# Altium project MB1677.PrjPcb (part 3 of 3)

## Sheet STM32_microcontroller_IOs.SchDoc: STM32 microcontroller IOs
size A3; Date: Not used; ApprovedBy: Not used; CheckedBy: Not used; Author: Not used; CompanyName: STMicroelectronics; DrawnBy: Not used; Engineer: Not used; Organization: Not used; Address1: Not used; Address2: Not used; Address3: Not used; Address4: Not used; DocumentNumber: 3; Revision: Not used; SheetNumber: 3; SheetTotal: 15
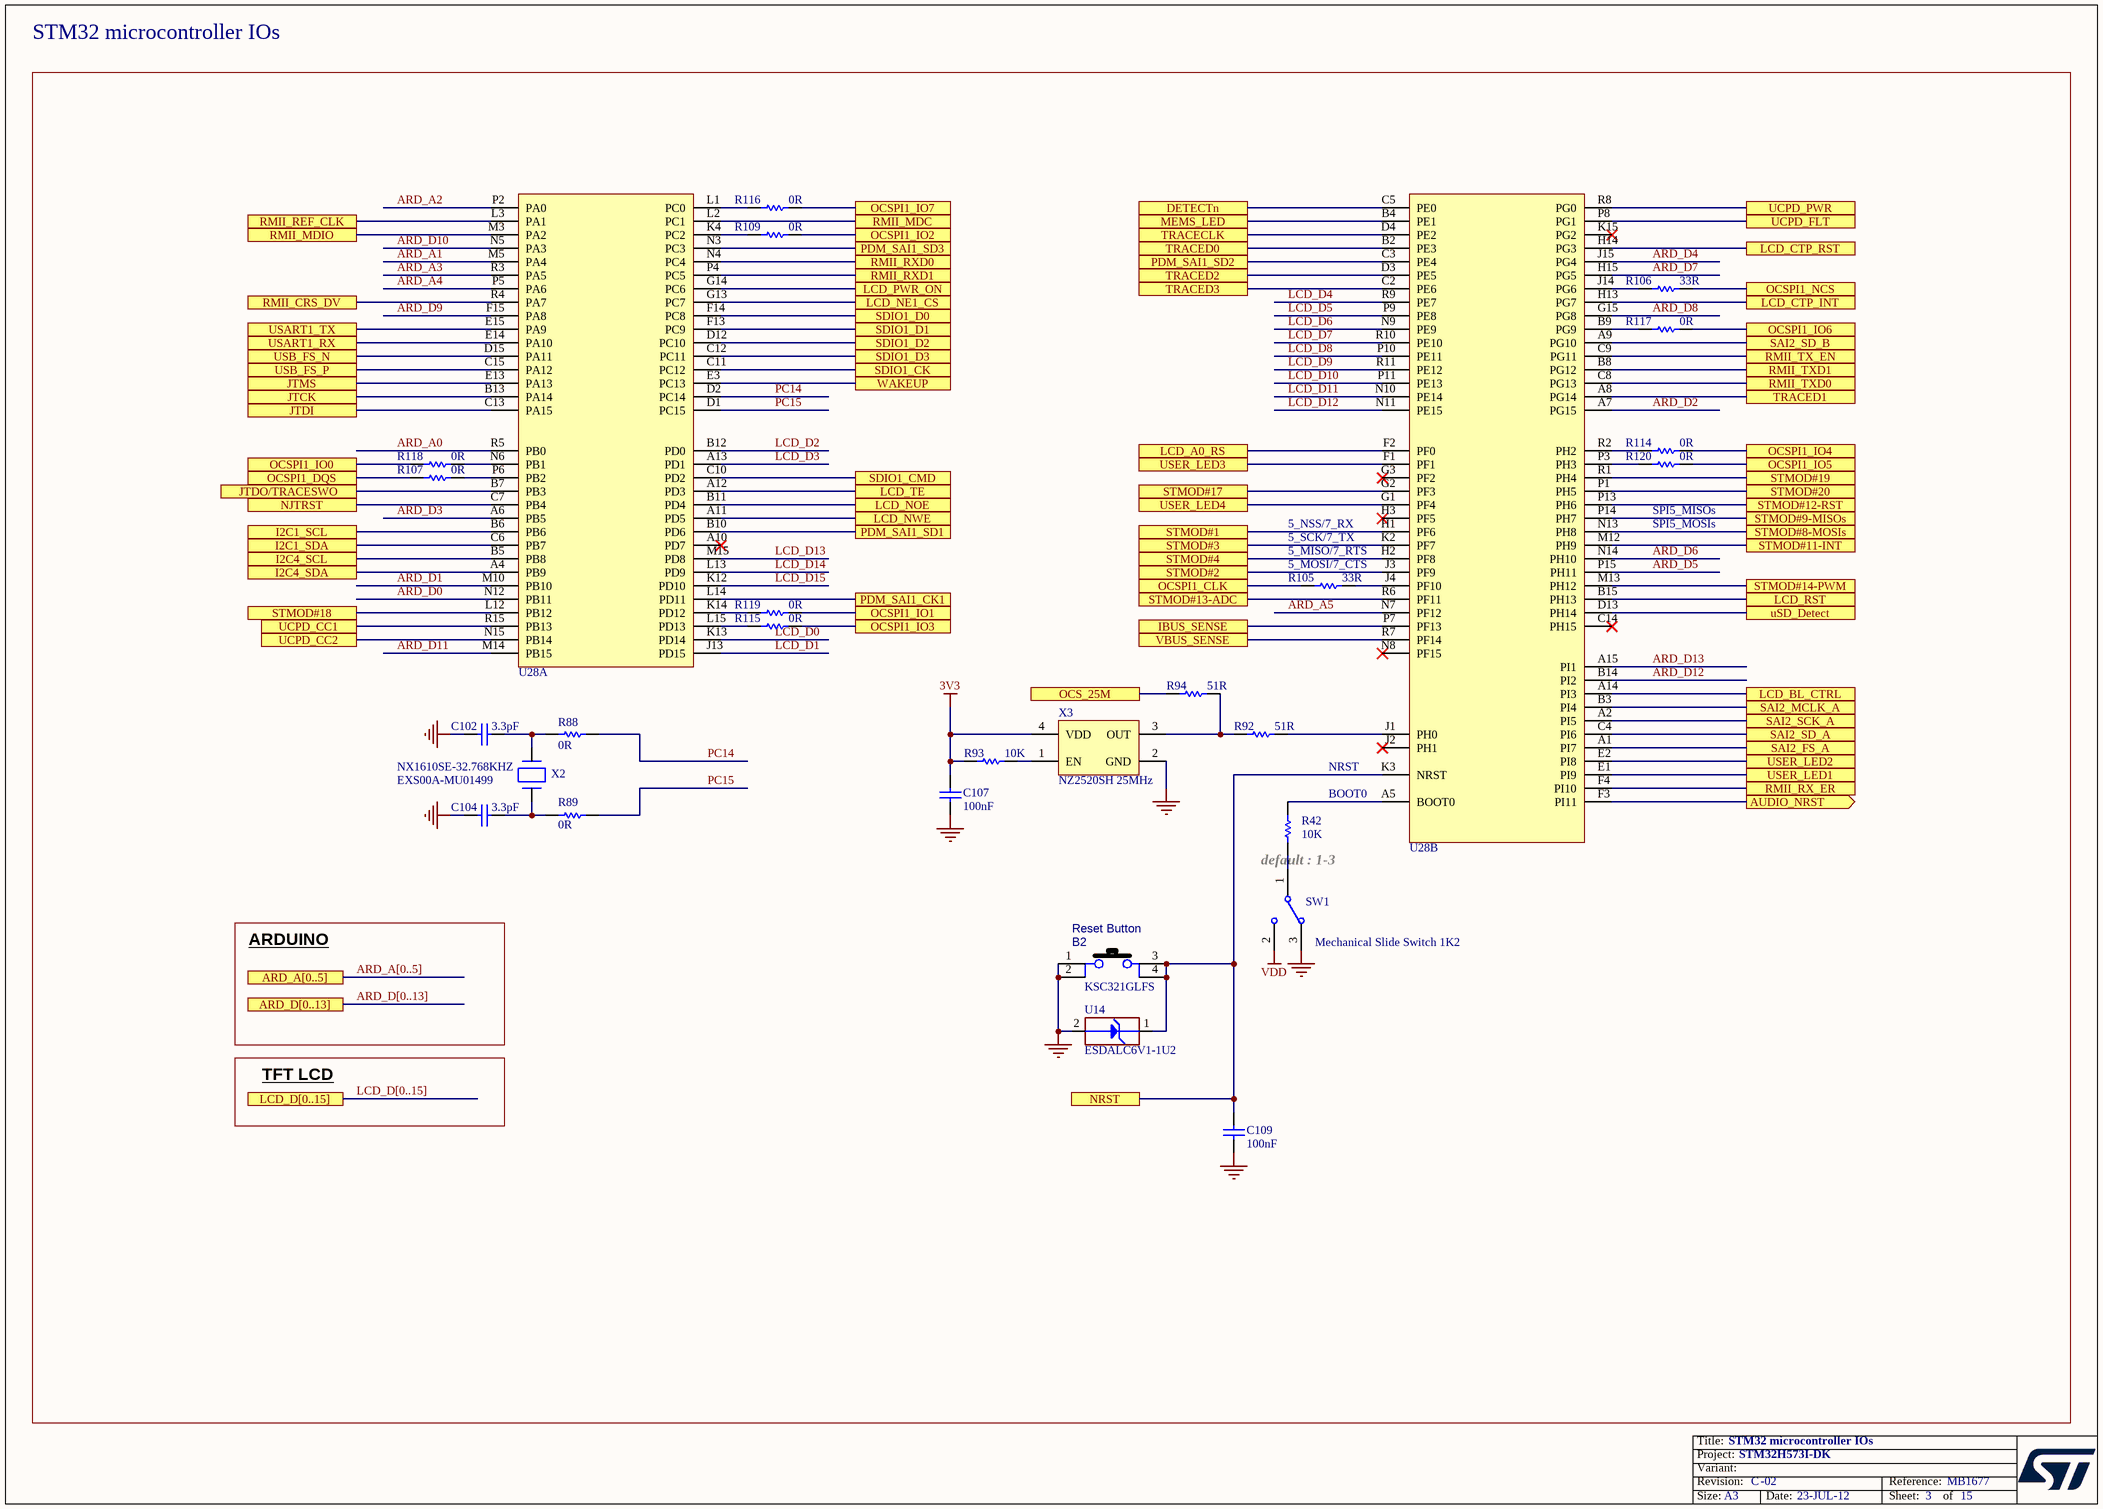
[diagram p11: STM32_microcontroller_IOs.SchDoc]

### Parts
B2  value KSC321GLFS  [SWI_C&K_KSC321GLFS_BLACK]  (hidden comment: SW_BLACK_KSC321GLFS)
C102  value 3.3pF  [C0402]  (hidden comment: Capacitor)
C104  value 3.3pF  [C0402]  (hidden comment: Capacitor)
C107  value 100nF  [C0402]  (hidden comment: Capacitor)
C109  value 100nF  [C0402]  (hidden comment: Capacitor)
R42  value 10K  [R0402]  (hidden comment: Resistor)
R88  value 0R  [R0402]  (hidden comment: Resistor)
R89  value 0R  [R0402]  (hidden comment: Resistor)
R92  value 51R  [R0402]  (hidden comment: Resistor)
R93  value 10K  [R0402]  (hidden comment: Resistor)
R94  value 51R  [R0402]  (hidden comment: Resistor)
R105  value 33R  [R0402]  (hidden comment: Resistor)
R106  value 33R  [R0402]  (hidden comment: Resistor)
R107  value 0R  [R0402]  (hidden comment: Resistor)
R109  value 0R  [R0402]  (hidden comment: Resistor)
R114  value 0R  [R0402]  (hidden comment: Resistor)
R115  value 0R  [R0402]  (hidden comment: Resistor)
R116  value 0R  [R0402]  (hidden comment: Resistor)
R117  value 0R  [R0402]  (hidden comment: Resistor)
R118  value 0R  [R0402]  (hidden comment: Resistor)
R119  value 0R  [R0402]  (hidden comment: Resistor)
R120  value 0R  [R0402]  (hidden comment: Resistor)
SW1  value Mechanical Slide Switch 1K2  [SWI_EAO_09-03290-01_EXTENDED_STRAIGHT_BLACK]  (hidden comment: SW_MECA_1K2)
U14  value ESDALC6V1-1U2  [ESD_ST0201]  (hidden comment: ESD-TRANSIL)
U28  STM32H573IIK3Q  [ICC_UFBGA201_176+25_10X10_P065]  (value not drawn)  (parts A,B of 3)
X2  XTAL_2_PINS  [CRY_NX1610SE_2P]  (value not drawn)
X3  value NZ2520SH 25MHz  [OSC_NDK_NZ2520SB_4P]  (hidden comment: OSCILLATOR_4_PINS)

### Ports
ARD_A[0..5], ARD_D[0..13], AUDIO_NRST (out), DETECTn, I2C1_SCL, I2C1_SDA, I2C4_SCL, I2C4_SDA, IBUS_SENSE, JTCK, JTDI, JTDO/TRACESWO, JTMS, LCD_A0_RS, LCD_BL_CTRL, LCD_CTP_INT, LCD_CTP_RST, LCD_D[0..15], LCD_NE1_CS, LCD_NOE, LCD_NWE, LCD_PWR_ON, LCD_RST, LCD_TE, MEMS_LED, NJTRST, NRST, OCS_25M, OCSPI1_CLK, OCSPI1_DQS, OCSPI1_IO0, OCSPI1_IO1, OCSPI1_IO2, OCSPI1_IO3, OCSPI1_IO4, OCSPI1_IO5, OCSPI1_IO6, OCSPI1_IO7, OCSPI1_NCS, PDM_SAI1_CK1, PDM_SAI1_SD1, PDM_SAI1_SD2, PDM_SAI1_SD3, RMII_CRS_DV, RMII_MDC, RMII_MDIO, RMII_REF_CLK, RMII_RX_ER, RMII_RXD0, RMII_RXD1, RMII_TX_EN, RMII_TXD0, RMII_TXD1, SAI2_FS_A, SAI2_MCLK_A, SAI2_SCK_A, SAI2_SD_A, SAI2_SD_B, SDIO1_CK, SDIO1_CMD, SDIO1_D0, SDIO1_D1, SDIO1_D2, SDIO1_D3, STMOD#1, STMOD#2, STMOD#3, STMOD#4, STMOD#8-MOSIs, STMOD#9-MISOs, STMOD#11-INT, STMOD#12-RST, STMOD#13-ADC, STMOD#14-PWM, STMOD#17, STMOD#18, STMOD#19, STMOD#20, TRACECLK, TRACED0, TRACED1, TRACED2, TRACED3, UCPD_CC1, UCPD_CC2, UCPD_FLT, UCPD_PWR, USART1_RX, USART1_TX, USB_FS_N, USB_FS_P, uSD_Detect, USER_LED1, USER_LED2, USER_LED3, USER_LED4, VBUS_SENSE, WAKEUP

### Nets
3V3: C107.2 R93.1 X3.4(VDD)
GND: B2.1 B2.2 C102.1 C104.1 C107.1 C109.1 SW1.3 U14.2(GND) X3.2(GND)
VDD: SW1.2
ARD_A0: U28.R5(PB0)
ARD_A1: U28.M5(PA4)
ARD_A2: U28.P2(PA0)
ARD_A3: U28.R3(PA5)
ARD_A4: U28.P5(PA6)
ARD_A5: U28.N7(PF12)
ARD_D0: U28.N12(PB11)
ARD_D1: U28.M10(PB10)
ARD_D2: U28.A7(PG15)
ARD_D3: U28.A6(PB5)
ARD_D4: U28.J15(PG4)
ARD_D5: U28.P15(PH11)
ARD_D6: U28.N14(PH10)
ARD_D7: U28.H15(PG5)
ARD_D8: U28.G15(PG8)
ARD_D9: U28.F15(PA8)
ARD_D10: U28.N5(PA3)
ARD_D11: U28.M14(PB15)
ARD_D12: U28.B14(PI2)
ARD_D13: U28.A15(PI1)
AUDIO_NRST: U28.F3(PI11) ; port AUDIO_NRST
DETECTn: U28.C5(PE0) ; port DETECTn
I2C1_SCL: U28.B6(PB6) ; port I2C1_SCL
I2C1_SDA: U28.C6(PB7) ; port I2C1_SDA
I2C4_SCL: U28.B5(PB8) ; port I2C4_SCL
I2C4_SDA: U28.A4(PB9) ; port I2C4_SDA
IBUS_SENSE: U28.P7(PF13) ; port IBUS_SENSE
JTCK: U28.B13(PA14) ; port JTCK
JTDI: U28.C13(PA15) ; port JTDI
JTDO: U28.B7(PB3) ; port JTDO/TRACESWO
JTMS: U28.E13(PA13) ; port JTMS
LCD_A0_RS: U28.F2(PF0) ; port LCD_A0_RS
LCD_BL_CTRL: U28.A14(PI3) ; port LCD_BL_CTRL
LCD_CTP_INT: U28.H13(PG7) ; port LCD_CTP_INT
LCD_CTP_RST: U28.H14(PG3) ; port LCD_CTP_RST
LCD_D0: U28.K13(PD14)
LCD_D1: U28.J13(PD15)
LCD_D2: U28.B12(PD0)
LCD_D3: U28.A13(PD1)
LCD_D4: U28.R9(PE7)
LCD_D5: U28.P9(PE8)
LCD_D6: U28.N9(PE9)
LCD_D7: U28.R10(PE10)
LCD_D8: U28.P10(PE11)
LCD_D9: U28.R11(PE12)
LCD_D10: U28.P11(PE13)
LCD_D11: U28.N10(PE14)
LCD_D12: U28.N11(PE15)
LCD_D13: U28.M15(PD8)
LCD_D14: U28.L13(PD9)
LCD_D15: U28.K12(PD10)
LCD_NE1_CS: U28.G13(PC7) ; port LCD_NE1_CS
LCD_NOE: U28.B11(PD4) ; port LCD_NOE
LCD_NWE: U28.A11(PD5) ; port LCD_NWE
LCD_PWR_ON: U28.G14(PC6) ; port LCD_PWR_ON
LCD_RST: U28.B15(PH13) ; port LCD_RST
LCD_TE: U28.A12(PD3) ; port LCD_TE
MEMS_LED: U28.B4(PE1) ; port MEMS_LED
NJTRST: U28.C7(PB4) ; port NJTRST
NRST: B2.3 B2.4 C109.2 U14.1(IO1) U28.K3(NRST) ; port NRST
OCS_25M: R94.1 ; port OCS_25M
OCSPI1_CLK: R105.1 ; port OCSPI1_CLK
OCSPI1_DQS: R107.1 ; port OCSPI1_DQS
OCSPI1_IO0: R118.1 ; port OCSPI1_IO0
OCSPI1_IO1: R119.2 ; port OCSPI1_IO1
OCSPI1_IO2: R109.2 ; port OCSPI1_IO2
OCSPI1_IO3: R115.2 ; port OCSPI1_IO3
OCSPI1_IO4: R114.2 ; port OCSPI1_IO4
OCSPI1_IO5: R120.2 ; port OCSPI1_IO5
OCSPI1_IO6: R117.2 ; port OCSPI1_IO6
OCSPI1_IO7: R116.2 ; port OCSPI1_IO7
OCSPI1_NCS: R106.2 ; port OCSPI1_NCS
PC14: R88.2 U28.D2(PC14)
PC15: R89.2 U28.D1(PC15)
PDM_SAI1_CK1: U28.L14(PD11) ; port PDM_SAI1_CK1
PDM_SAI1_SD1: U28.B10(PD6) ; port PDM_SAI1_SD1
PDM_SAI1_SD2: U28.C3(PE4) ; port PDM_SAI1_SD2
PDM_SAI1_SD3: U28.N3(PC3) ; port PDM_SAI1_SD3
PMOD11: U28.M12(PH9) ; port STMOD#11-INT
PMOD12: U28.P13(PH6) ; port STMOD#12-RST
RMII_CRS_DV: U28.R4(PA7) ; port RMII_CRS_DV
RMII_MDC: U28.L2(PC1) ; port RMII_MDC
RMII_MDIO: U28.M3(PA2) ; port RMII_MDIO
RMII_REF_CLK: U28.L3(PA1) ; port RMII_REF_CLK
RMII_RX_ER: U28.F4(PI10) ; port RMII_RX_ER
RMII_RXD0: U28.N4(PC4) ; port RMII_RXD0
RMII_RXD1: U28.P4(PC5) ; port RMII_RXD1
RMII_TX_EN: U28.C9(PG11) ; port RMII_TX_EN
RMII_TXD0: U28.C8(PG13) ; port RMII_TXD0
RMII_TXD1: U28.B8(PG12) ; port RMII_TXD1
SAI2_FS_A: U28.A1(PI7) ; port SAI2_FS_A
SAI2_MCLK_A: U28.B3(PI4) ; port SAI2_MCLK_A
SAI2_SCK_A: U28.A2(PI5) ; port SAI2_SCK_A
SAI2_SD_A: U28.C4(PI6) ; port SAI2_SD_A
SAI2_SD_B: U28.A9(PG10) ; port SAI2_SD_B
SDIO1_CK: U28.C11(PC12) ; port SDIO1_CK
SDIO1_CMD: U28.C10(PD2) ; port SDIO1_CMD
SDIO1_D0: U28.F14(PC8) ; port SDIO1_D0
SDIO1_D1: U28.F13(PC9) ; port SDIO1_D1
SDIO1_D2: U28.D12(PC10) ; port SDIO1_D2
SDIO1_D3: U28.C12(PC11) ; port SDIO1_D3
STMOD#1: U28.H1(PF6) ; port STMOD#1
STMOD#2: U28.J3(PF9) ; port STMOD#2
STMOD#3: U28.K2(PF7) ; port STMOD#3
STMOD#4: U28.H2(PF8) ; port STMOD#4
STMOD#8-MOSIs: U28.N13(PH8) ; port STMOD#8-MOSIs
STMOD#9-MISOs: U28.P14(PH7) ; port STMOD#9-MISOs
STMOD#13-ADC: U28.R6(PF11) ; port STMOD#13-ADC
STMOD#14-PWM: U28.M13(PH12) ; port STMOD#14-PWM
STMOD#17: U28.G2(PF3) ; port STMOD#17
STMOD#18: U28.L12(PB12) ; port STMOD#18
STMOD#19: U28.R1(PH4) ; port STMOD#19
STMOD#20: U28.P1(PH5) ; port STMOD#20
TRACECLK: U28.D4(PE2) ; port TRACECLK
TRACED0: U28.B2(PE3) ; port TRACED0
TRACED1: U28.A8(PG14) ; port TRACED1
TRACED2: U28.D3(PE5) ; port TRACED2
TRACED3: U28.C2(PE6) ; port TRACED3
UCPD_CC1: U28.R15(PB13) ; port UCPD_CC1
UCPD_CC2: U28.N15(PB14) ; port UCPD_CC2
UCPD_FLT: U28.P8(PG1) ; port UCPD_FLT
UCPD_PWR: U28.R8(PG0) ; port UCPD_PWR
USART1_RX: U28.E14(PA10) ; port USART1_RX
USART1_TX: U28.E15(PA9) ; port USART1_TX
USB_FS_N: U28.D15(PA11) ; port USB_FS_N
USB_FS_P: U28.C15(PA12) ; port USB_FS_P
uSD_Detect: U28.D13(PH14) ; port uSD_Detect
USER_LED1: U28.E1(PI9) ; port USER_LED1
USER_LED2: U28.E2(PI8) ; port USER_LED2
USER_LED3: U28.F1(PF1) ; port USER_LED3
USER_LED4: U28.G1(PF4) ; port USER_LED4
VBUS_SENSE: U28.R7(PF14) ; port VBUS_SENSE
WAKEUP: U28.E3(PC13) ; port WAKEUP
NetC102_2: C102.2 R88.1 X2.2(X2)
NetC104_2: C104.2 R89.1 X2.1(X1)
NetR42_1: R42.1 U28.A5(BOOT0)
NetR42_2: R42.2 SW1.1
NetR92_1: R92.1 R94.2 X3.3(OUT)
NetR92_2: R92.2 U28.J1(PH0)
NetR93_2: R93.2 X3.1(EN)
NetR105_2: R105.2 U28.J4(PF10)
NetR106_1: R106.1 U28.J14(PG6)
NetR107_2: R107.2 U28.P6(PB2)
NetR109_1: R109.1 U28.K4(PC2)
NetR114_1: R114.1 U28.R2(PH2)
NetR115_1: R115.1 U28.L15(PD13)
NetR116_1: R116.1 U28.L1(PC0)
NetR117_1: R117.1 U28.B9(PG9)
NetR118_2: R118.2 U28.N6(PB1)
NetR119_1: R119.1 U28.K14(PD12)
NetR120_1: R120.1 U28.P3(PH3)

Not connected (* = marked no-connect by the designer): U28 A10(PD7)* C14(PH15)* G3(PF2)* H3(PF5)* J2(PH1)* K15(PG2)* N8(PF15)*

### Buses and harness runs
bus ARD_A[0..5] = port ARD_A[0..5]
bus ARD_D[0..13] = port ARD_D[0..13]
bus LCD_D[0..15] = port LCD_D[0..15]

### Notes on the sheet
- STM32 microcontroller IOs
- SPI5_MISOs
- 5_NSS/7_RX
- 5_SCK/7_TX
- (near R105) 5_MISO/7_RTS
- (near R105) 5_MOSI/7_CTS
- SPI5_MOSIs
- EXS00A-MU01499
- NX1610SE-32.768KHZ
- NRST
- BOOT0
- (near R42) default : 1-3
- ARDUINO
- (near B2) Reset Button
- TFT LCD

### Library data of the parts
B2 = MCD-00175: Switch HW BLACK High3.5mm 2Newtons; Part_Type: Misc; Part_Preference: Recommended; Manufacturer: C&K; Component_Country_Of_Origin: France; ShowFields: YES; ID: 2692
C102 C104 = MCD-01775: Capacitor, MLCC, 3.3pF, 50V, NPO, +/-0.1pF, 0402, T=0.5mm; Part_Preference: Recommended; Manufacturer: YAGEO; Manufacturer_Part_Number: CC0402BRNPO9BN3R3; Component_Country_Of_Origin: China; ShowFields: YES; ID: 3875
C107 = MCD-00102: Capacitor, MLCC, 100nF, 16V, X7R, 10%, 0402, T=0,5mm; Manufacturer_Part_Number: CC0402KRX7R7BB104; Manufacturer: YAGEO; Alternate_Manufacturer_Part_Number: GCM155R71C104KA55D; Alternate_Manufacturer: MURATA; ECCN_US: EAR99; ECCN_EU: NEC; Provided_By: SUBCO
C109 = MCD-00006: Capacitor, MLCC, 100nF, 16V, X7R, 10%, 0402, T=0.5mm; Manufacturer_Part_Number: CC0402KRX7R7BB104; Manufacturer: YAGEO; Alternate_Manufacturer_Part_Number: GCM155R71C104KA55D; Alternate_Manufacturer: MURATA; Provided_By: SUBCO
R42 = MCD-00053: Resistor,10K,0402,1%,1/16W; Manufacturer_Part_Number: RC0402FR-0710KL; Manufacturer: YAGEO; Provided_By: SUBCO
R88 R89 R107 R109 R114-R120 = MCD-00052: Resistor,0R,0402,5%,1/16W; Manufacturer_Part_Number: RC0402JR-070RL; Manufacturer: YAGEO; Provided_By: SUBCO
R92 R94 = MCD-00485: Resistor,51R,0402,1%,1/16W; Manufacturer_Part_Number: RC0402FR-0751RL; Manufacturer: YAGEO; ECCN_US: EAR99; ECCN_EU: NEC; Provided_By: SUBCO
R93 = MCD-00053: Resistor,10K,0402,1%,1/16W; Manufacturer_Part_Number: RC0402FR-0710KL; Manufacturer: YAGEO; BMS_Part_Number: 9131590; ECCN_US: EAR99; ECCN_EU: NEC; Provided_By: SUBCO
R105 R106 = MCD-00455: Resistor,33R,0402,1%,1/16W; Manufacturer_Part_Number: RC0402FR-0733RL; Manufacturer: YAGEO; Provided_By: SUBCO; ECCN_US: EAR99; ECCN_EU: NEC
SW1 = MCD-00566: Mechanical Slide Switches 1K2 BLK ACT GOLD STRT MNT; Part_Type: Misc; Manufacturer_Part_Number: 09.03290.01; Manufacturer: EAO; Provided_By: SUBCO
U14 = MCD-00170: ESD protection 6V1; Part_Type: Diode; Manufacturer: STMICROELECTRONICS; BMS_Part_Number: 9151132; Provided_By: SUBCO with ST control
U28 = MCD-02379: MCU, Arm Cortex-M33, 250MHz, 32-bit MCU, 2MB Flash, 640KB SRAM, Crypto; Part_Type: IC; Manufacturer: STMICROELECTRONICS; Part_Preference: Recommended
X2 = MCD-02291: Crystal, 32.768kHz, 9pF, +/-20ppm, 70KR, 1.6x1mm; Part_Type: Crystal_Osc; Part_Preference: Recommended; Manufacturer: NDK; Manufacturer_Part_Number: NX1610SE-32.768KHZ-EXS00A-MU01499; Component_Country_Of_Origin: Unknown; ShowFields: YES; ID: 4391
X3 = MCD-00597: Oscillator 25Mhz, +-50ppm, Vcc:3.3V typ, square wave: [0.1Vcc;0.9Vcc], Enable pin, SMD; Part_Type: Crystal_Osc; Manufacturer_Part_Number: NZ2520SH 25MHz END4869C; Manufacturer: NDK; Alternate_Manufacturer_Part_Number: NZ2520SB 25MHz END4869B; BMS_Part_Number: 9157050; ECCN_US: EAR99; ECCN_EU: NEC; Provided_By: SUBCO

## Sheet USB-PD.SchDoc: USB-PD
size A3; Date: Not used; ApprovedBy: Not used; CheckedBy: Not used; Author: Not used; CompanyName: STMicroelectronics; DrawnBy: Not used; Engineer: Not used; Organization: Not used; Address1: Not used; Address2: Not used; Address3: Not used; Address4: Not used; DocumentNumber: 13; Revision: Not used; SheetNumber: 13; SheetTotal: 15
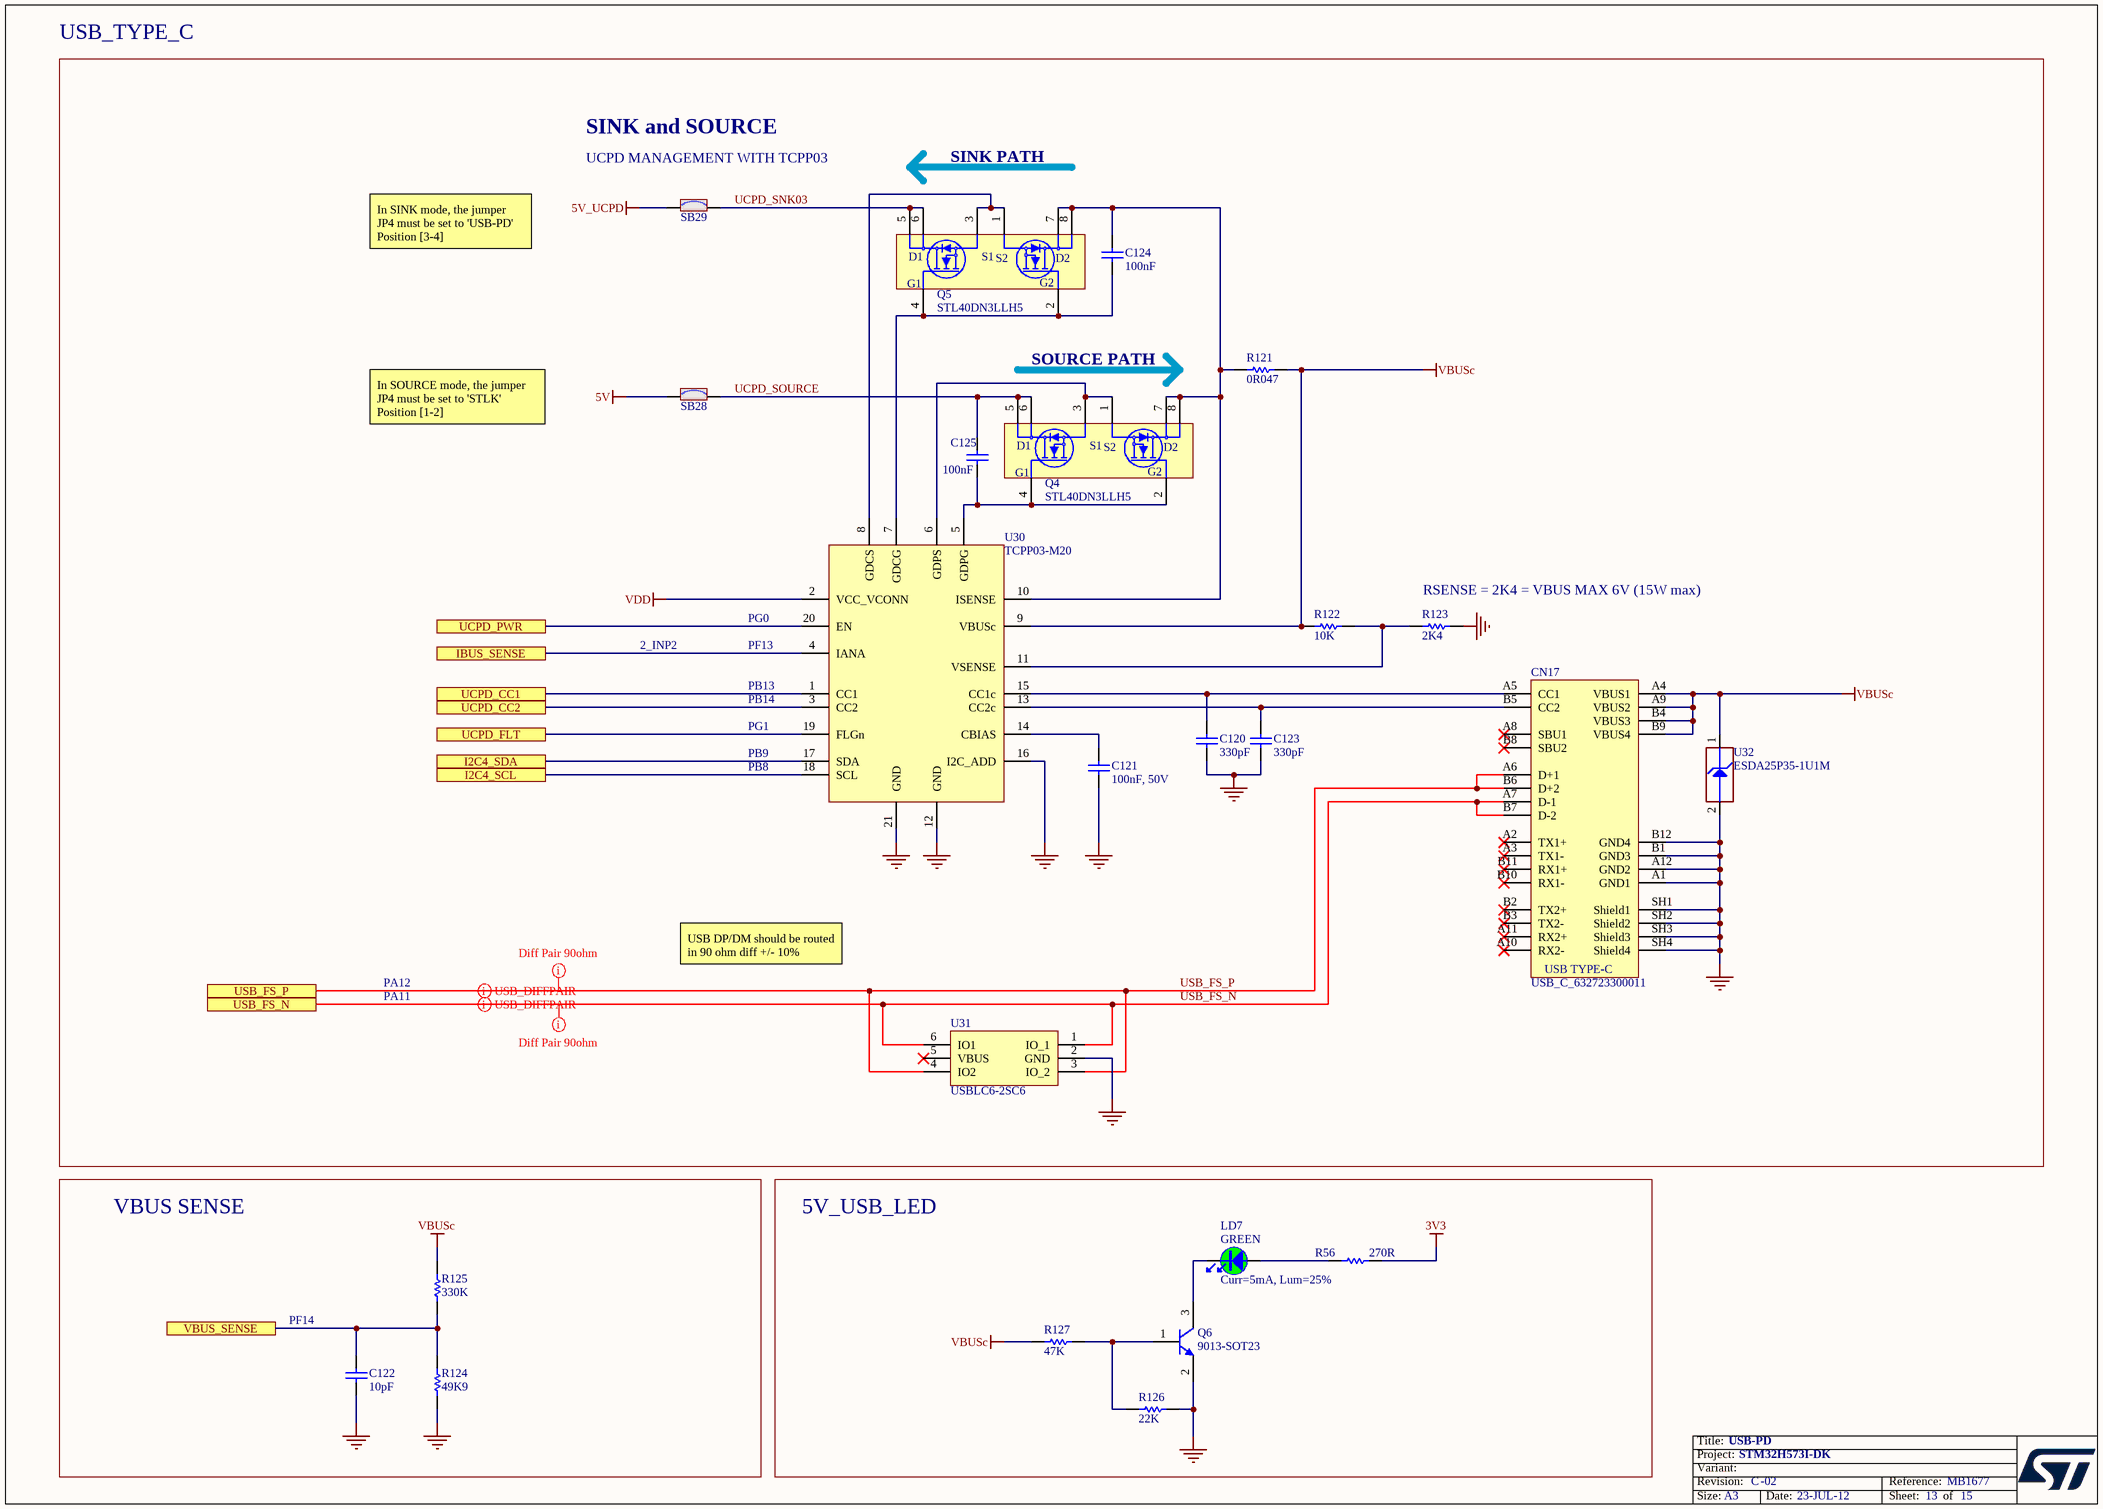
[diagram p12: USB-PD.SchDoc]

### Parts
C120  value 330pF  [C0402]  (hidden comment: Capacitor)
C121  value 100nF, 50V  [C0603]
C122  value 10pF  [C0402]
C123  value 330pF  [C0402]  (hidden comment: Capacitor)
C124  value 100nF  [C0603]
C125  value 100nF  [C0603]
CN17  value USB_C_632723300011  [CON_USB-TYPEC_WE_632723300011]  (hidden comment: USB_TYPE_C_Receptacle)
LD7  value GREEN  [LED_0603_OSRAM_LG-Q396-PS-35_GREEN_1A2K_H0P4]
Q4  STL40DN3LLH5  [PowerFLAT_5x6]
Q5  STL40DN3LLH5  [PowerFLAT_5x6]
Q6  value 9013-SOT23  [NPN_SOT23]
R56  value 270R  [R0603]
R121  value 0R047  [R0805_H0P5]  (hidden comment: Resistor)
R122  value 10K  [R0402]  (hidden comment: Resistor)
R123  value 2K4  [R0402]  (hidden comment: Resistor)
R124  value 49K9  [R0603]
R125  value 330K  [R0603]
R126  value 22K  [R0603]
R127  value 47K  [R0603]
SB28  SB_ON  [SOLDER-BRIDGE_R0603-0R]  (value not drawn)
SB29  SB_ON  [SOLDER-BRIDGE_R0603-0R]  (value not drawn)
U30  TCPP03-M20  [ICC_QFN20-EPAD_4X4_P050]
U31  USBLC6-2SC6  [ESD_SOT23-6L]
U32  value ESDA25P35-1U1M  [ESD_QFN1610_2N_1K_2A]

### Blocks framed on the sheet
VBUS SENSE: C122 R124 R125
5V_USB_LED: LD7 Q6 R56 R126 R127

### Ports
I2C4_SCL, I2C4_SDA, IBUS_SENSE, UCPD_CC1, UCPD_CC2, UCPD_FLT, UCPD_PWR, USB_FS_N, USB_FS_P, VBUS_SENSE

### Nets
3V3: R56.2
5V: SB28.1
5V_UCPD: SB29.1
GND: C120.1 C121.2 C122.1 C123.1 CN17.A1(GND1) CN17.A12(GND2) CN17.B1(GND3) CN17.B12(GND4) CN17.SH1(Shield1) CN17.SH2(Shield2) CN17.SH3(Shield3) CN17.SH4(Shield4) Q6.2(E) R123.2 R124.1 R126.2 U30.12(GND) U30.16(I2C_ADD) U30.21(GND) U31.2(GND) U32.2(GND)
VBUSc: CN17.A4(VBUS1) CN17.A9(VBUS2) CN17.B4(VBUS3) CN17.B9(VBUS4) R121.1 R122.1 R125.2 R127.1 U30.9(VBUSc) U32.1(IO1)
VDD: U30.2(VCC_VCONN)
I2C4_SCL: U30.18(SCL) ; port I2C4_SCL
I2C4_SDA: U30.17(SDA) ; port I2C4_SDA
IBUS_SENSE: U30.4(IANA) ; port IBUS_SENSE
UCPD_CC1: U30.1(CC1) ; port UCPD_CC1
UCPD_CC2: U30.3(CC2) ; port UCPD_CC2
UCPD_FLT: U30.19(FLGn) ; port UCPD_FLT
UCPD_PWR: U30.20(EN) ; port UCPD_PWR
UCPD_SNK03: Q5.5(D1) Q5.6(D1) SB29.2
UCPD_SOURCE: C125.2 Q4.5(D1) Q4.6(D1) SB28.2
USB_FS_N: CN17.A7(D-1) CN17.B7(D-2) U31.1(IO_1) U31.6(IO1) ; port USB_FS_N
USB_FS_P: CN17.A6(D+1) CN17.B6(D+2) U31.3(IO_2) U31.4(IO2) ; port USB_FS_P
VBUS_SENSE: C122.2 R124.2 R125.1 ; port VBUS_SENSE
NetC120_2: C120.2 CN17.A5(CC1) U30.15(CC1c)
NetC121_1: C121.1 U30.14(CBIAS)
NetC123_2: C123.2 CN17.B5(CC2) U30.13(CC2c)
NetC124_1: C124.1 Q5.2(G2) Q5.4(G1) U30.7(GDCG)
NetC124_2: C124.2 Q4.7(D2) Q4.8(D2) Q5.7(D2) Q5.8(D2) R121.2 U30.10(ISENSE)
NetC125_1: C125.1 Q4.2(G2) Q4.4(G1) U30.5(GDPG)
NetLD7_1: LD7.1 R56.1
NetLD7_2: LD7.2 Q6.3(C)
NetQ4_1: Q4.1(S2) Q4.3(S1) U30.6(GDPS)
NetQ5_1: Q5.1(S2) Q5.3(S1) U30.8(GDCS)
NetQ6_1: Q6.1(B) R126.1 R127.2
NetR122_2: R122.2 R123.1 U30.11(VSENSE)

Not connected (* = marked no-connect by the designer): CN17 A2(TX1+)* A3(TX1-)* A8(SBU1)* A10(RX2-)* A11(RX2+)* B2(TX2+)* B3(TX2-)* B8(SBU2)* B10(RX1-)* B11(RX1+)*; U31 5(VBUS)*

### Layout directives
mark named Diff Pair 90ohm: USB_FS_N, USB_FS_P
differential pair: USB_FS_N, USB_FS_P

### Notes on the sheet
- USB_TYPE_C
- (near SB29) UCPD MANAGEMENT WITH TCPP03
- SINK and SOURCE
- SINK PATH
- In SINK mode, the jumper JP4 must be set to 'USB-PD' Position [3-4]
- SOURCE PATH
- In SOURCE mode, the jumper JP4 must be set to 'STLK' Position [1-2]
- 2_INP2
- PF13
- PG0
- (near R123) RSENSE = 2K4 = VBUS MAX 6V (15W max)
- PB13
- PB14
- PB9
- PB8
- PG1
- PA12
- USB DP/DM should be routed in 90 ohm diff +/- 10%
- PA11
- PF14
- Curr=5mA, Lum=25%

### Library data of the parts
C120 C123 = MCD-01579: Capacitor, MLCC, 330pF, 50V, NPO, +/-5%, 0402, T=0,5mm; Part_Preference: Recommended; Manufacturer: YAGEO; Manufacturer_Part_Number: CC0402JRNPO9BN331
C121 = MCD-01099: Capacitor,100nF,50V,X7R,10%,0603; Manufacturer_Part_Number: CC0603KRX7R9BB104; Manufacturer: YAGEO; BMS_Part_Number: 9142278; Provided_By: SUBCO
C122 = MCD-00015: Capacitor, MLCC, 10pF, 50V, NPO, 5%, 0402, T=0,5mm; Manufacturer_Part_Number: CC0402JRNPO9BN100; Manufacturer: YAGEO; Provided_By: subcon; Initial_Board_Reference: MB1274
C124 C125 = MCD-00211: Capacitor, MLCC, 100nF, 16V, X7R, 10%, 0603, T=0,8mm; Manufacturer_Part_Number: CC0603KRX7R7BB104; Manufacturer: YAGEO; Provided_By: Subcon; Initial_Board_Reference: MB1319
CN17 = MCD-02273: USB_TypeC, 24pins, RA, TH, T=1.9mm (USB certified); Part_Type: Connector; Part_Preference: Recommended; Manufacturer: WURTH ELEKTRONIK; Manufacturer_Part_Number: 632723300011; Component_Country_Of_Origin: China; ShowFields: YES; ID: 4373
LD7 = MCD-00588: LED Green, 0603 SMD, Forward Voltage Typ=2V, Max=2.5V; Part_Type: Display; Manufacturer_Part_Number: LG Q396-PS-35; Manufacturer: OSRAM OPTO SEMICONDUCTORS; Alternate_Manufacturer_Part_Number: VLMTG1300-GS08; Alternate_Manufacturer: VISHAY SEMICONDUCTOR OPTO DIVISION; Provided_By: Subcon; Initial_Board_Reference: MB1331
Q4 Q5 = MCD-02152: Dual N-channel 30 V, 0.016 Ω typ., 40 A, STripFET™ H5 Power MOSFET; Part_Type: Transistor; Manufacturer: STMICROELECTRONICS; ECCN_US: EAR99; ECCN_EU: NEC; Provided_By: SUBCO
Q6 = MCD-00073: NPN Bipolar Transistor; Part_Type: IC; Manufacturer_Part_Number: BSR14; Manufacturer: NXP; ECCN_US: EAR99; ECCN_EU: NEC; Provided_By: Subcon; Initial_Board_Reference: MB1274
R56 = MCD-00442: Resistor,270R,0603,1%,1/10W; Manufacturer_Part_Number: RC0603FR-07270RL; Manufacturer: YAGEO; Provided_By: Subcon
R121 = MCD-02151: Current Detection Resistor, 0R047, 0805, 1%, 1/4W; Manufacturer_Part_Number: RL0805FR-7W0R047L; Manufacturer: YAGEO; ECCN_US: NEC; ECCN_EU: EAR99; Provided_By: SUBCO
R122 = MCD-00053: Resistor,10K,0402,1%,1/16W; BMS_Part_Number: 9131590; Part_Preference: Recommended; Manufacturer: YAGEO; Manufacturer_Part_Number: RC0402FR-0710KL
R123 = MCD-00433: Resistor,2K4,0402,1%,1/16W; Part_Preference: Recommended; Manufacturer: YAGEO; Manufacturer_Part_Number: RC0402FR-072K4L
R124 = MCD-01171: Resistor,49K9,0603,1%; Manufacturer_Part_Number: RC0603FR-0749K9L; Manufacturer: YAGEO; Provided_By: Subcon; Initial_Board_Reference: MB1397
R125 = MCD-00458: Resistor,330K,0603,1%,1/10W; Manufacturer_Part_Number: RC0603FR-07330KL; Manufacturer: YAGEO; Provided_By: Subcon
R126 = MCD-00430: Resistor,22K,0603,1%,1/10W; Manufacturer_Part_Number: RC0603FR-0722KL; Manufacturer: YAGEO; Provided_By: Subcon
R127 = MCD-00222: Resistor,47K,0603,1%,1/10W; Manufacturer_Part_Number: RC0603FR-0747KL; Manufacturer: YAGEO; Provided_By: Subcon; Initial_Board_Reference: MB1319
SB28 SB29 = MCD-00071: Solder Bridge ON; Part_Type: Mechanical; Manufacturer_Part_Number: RC0603JR-070RL; Manufacturer: YAGEO; Provided_By: SUBCO
U30 = MCD-02130: USB Type-C Port Protection for USB DRP Power Delivery, PPS compliant; Part_Type: IC; Manufacturer: STMICROELECTRONICS; ECCN_US: EAR99; ECCN_EU: NEC; Provided_By: SUBCO with ST control
U31 = MCD-00163: Very low capacitance ESD protection; Part_Type: IC; Manufacturer: STMICROELECTRONICS; BMS_Part_Number: 9151075; ECCN_US: EAR99; ECCN_EU: NEC; Provided_By: SUBCO with ST control
U32 = MCD-01207: High power Transient voltage suppressor:25V/35A EOS and ESD transients protection.; Part_Type: Diode; Manufacturer: STMICROELECTRONICS; BMS_Part_Number: 9179045; ECCN_US: EAR99; ECCN_EU: NEC; Provided_By: SUBCO with ST control

## Sheet microSDcard.SchDoc: microSD Card
size A4; Date: Not used; ApprovedBy: Not used; CheckedBy: Not used; Author: Not used; CompanyName: STMicroelectronics; DrawnBy: Not used; Engineer: Not used; Organization: Not used; Address1: Not used; Address2: Not used; Address3: Not used; Address4: Not used; DocumentNumber: 7; Revision: Not used; SheetNumber: 7; SheetTotal: 15
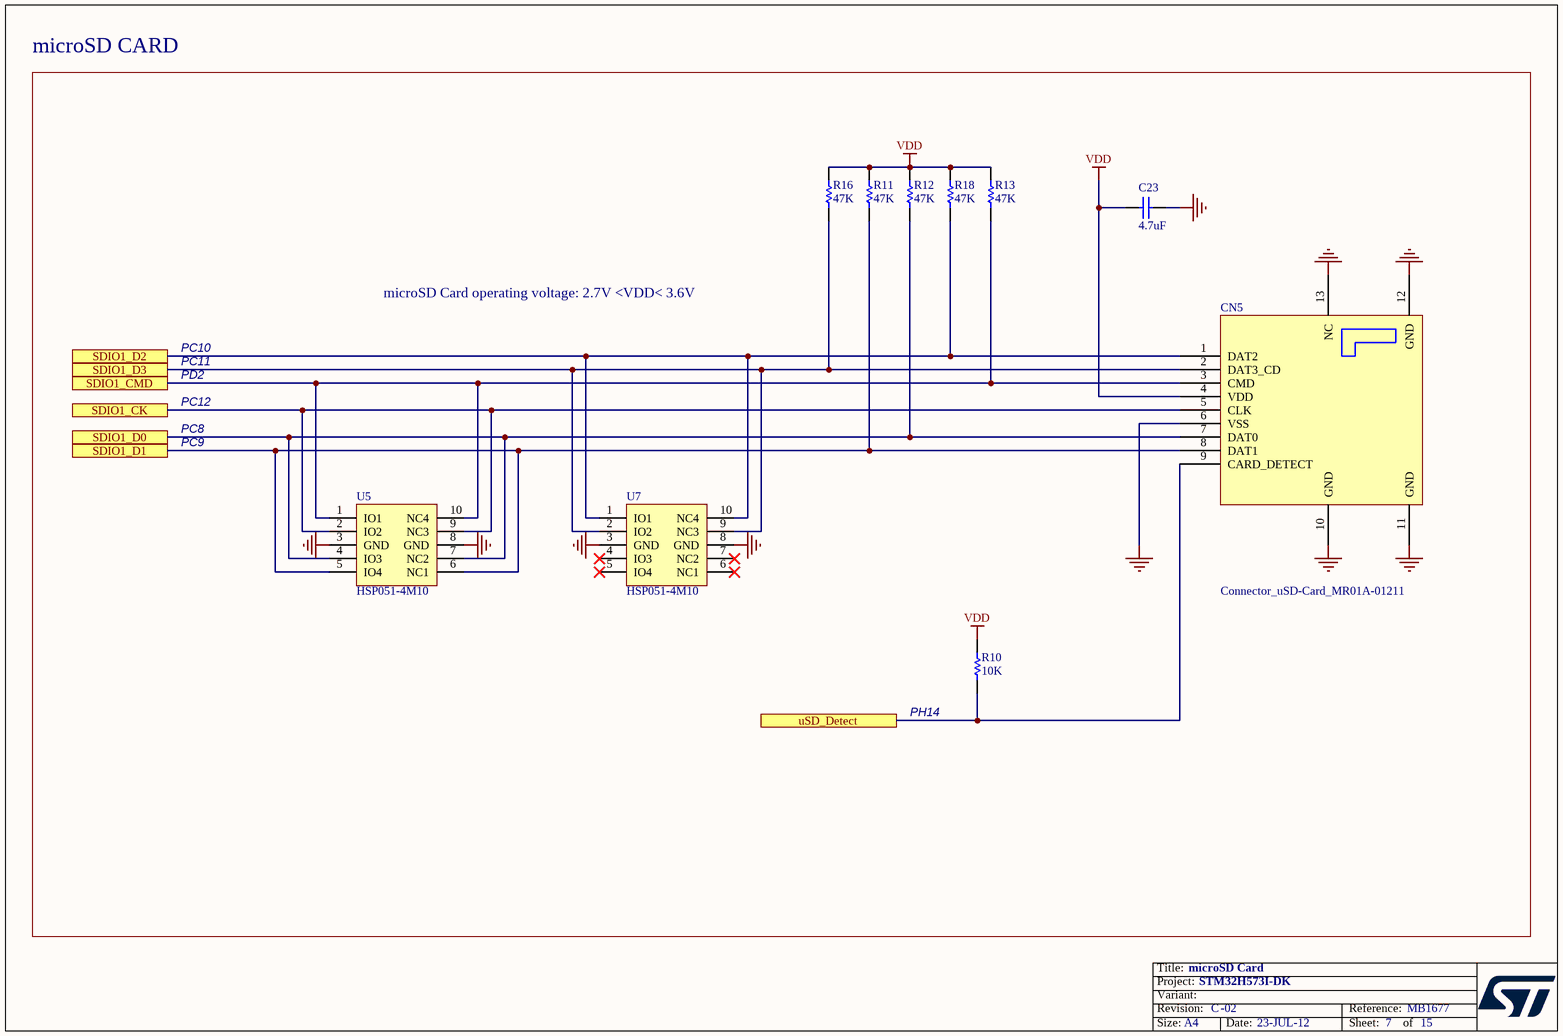
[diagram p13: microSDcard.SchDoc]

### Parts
C23  value 4.7uF  [C0603_H0P8]  (hidden comment: Capacitor)
CN5  value Connector_uSD-Card_MR01A-01211  [CON_MICROSD_ATOM_MR01A-01211]  (hidden comment: MR01A-01211)
R10  value 10K  [R0603]  (hidden comment: Resistor)
R11  value 47K  [R0402]  (hidden comment: Resistor)
R12  value 47K  [R0402]  (hidden comment: Resistor)
R13  value 47K  [R0402]  (hidden comment: Resistor)
R16  value 47K  [R0402]  (hidden comment: Resistor)
R18  value 47K  [R0402]  (hidden comment: Resistor)
U5  HSP051-4M10  [ESD_UQFN-10L_2P5X1_P050]
U7  HSP051-4M10  [ESD_UQFN-10L_2P5X1_P050]

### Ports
SDIO1_CK, SDIO1_CMD, SDIO1_D0, SDIO1_D1, SDIO1_D2, SDIO1_D3, uSD_Detect

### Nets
GND: C23.2 CN5.6(VSS) CN5.10(GND) CN5.11(GND) CN5.12(GND) CN5.13(NC) U5.3(GND) U5.8(GND) U7.3(GND) U7.8(GND)
VDD: C23.1 CN5.4(VDD) R10.2 R11.2 R12.2 R13.2 R16.2 R18.2
SDIO1_CK: CN5.5(CLK) U5.2(IO2) U5.9(NC3) ; port SDIO1_CK
SDIO1_CMD: CN5.3(CMD) R13.1 U5.1(IO1) U5.10(NC4) ; port SDIO1_CMD
SDIO1_D0: CN5.7(DAT0) R12.1 U5.4(IO3) U5.7(NC2) ; port SDIO1_D0
SDIO1_D1: CN5.8(DAT1) R11.1 U5.5(IO4) U5.6(NC1) ; port SDIO1_D1
SDIO1_D2: CN5.1(DAT2) R18.1 U7.1(IO1) U7.10(NC4) ; port SDIO1_D2
SDIO1_D3: CN5.2(DAT3_CD) R16.1 U7.2(IO2) U7.9(NC3) ; port SDIO1_D3
uSD_Detect: CN5.9(CARD_DETECT) R10.1 ; port uSD_Detect

Not connected (* = marked no-connect by the designer): U7 4(IO3)* 5(IO4)* 6(NC1)* 7(NC2)*

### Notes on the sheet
- microSD CARD
- microSD Card operating voltage: 2.7V <VDD< 3.6V
- PC10
- PC11
- PD2
- PC8
- PC9
- PC12
- (near R10) PH14

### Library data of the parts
C23 = MCD-01721: Capacitor, 4.7uF, 10V, X5R, 10%, 0603, T=0.8mm; Manufacturer_Part_Number: CC0603KRX5R6BB475; Manufacturer: YAGEO; Provided_By: SUBCO
CN5 = MCD-00653: Connector_uSD Card, Top Mnt Push-Push; Part_Preference: Recommended; Manufacturer: ATOM; Component_Country_Of_Origin: Unknown; ShowFields: YES; ID: 3087
R10 = MCD-00220: Resistor,10K,0603,1%,1/10W; Manufacturer_Part_Number: RC0603FR-0710KL; Manufacturer: YAGEO; Provided_By: SUBCO
R11-R13 R16 R18 = MCD-00063: Resistor,47K,0402,1%,1/16W; Manufacturer_Part_Number: RC0402FR-0747KL; Manufacturer: YAGEO; Provided_By: SUBCO
U5 U7 = MCD-00667: 4-line ESD protection for high speed lines; Part_Type: Diode; Manufacturer: STMICROELECTRONICS; BMS_Part_Number: 9179041; Provided_By: SUBCO with ST control

## Sheet NOR Flash memory.SchDoc: NOR Flash memory
size A4; Date: Not used; ApprovedBy: Not used; CheckedBy: Not used; Author: Not used; CompanyName: STMicroelectronics; DrawnBy: Not used; Engineer: Not used; Organization: Not used; Address1: Not used; Address2: Not used; Address3: Not used; Address4: Not used; DocumentNumber: 6; Revision: Not used; SheetNumber: 6; SheetTotal: 15
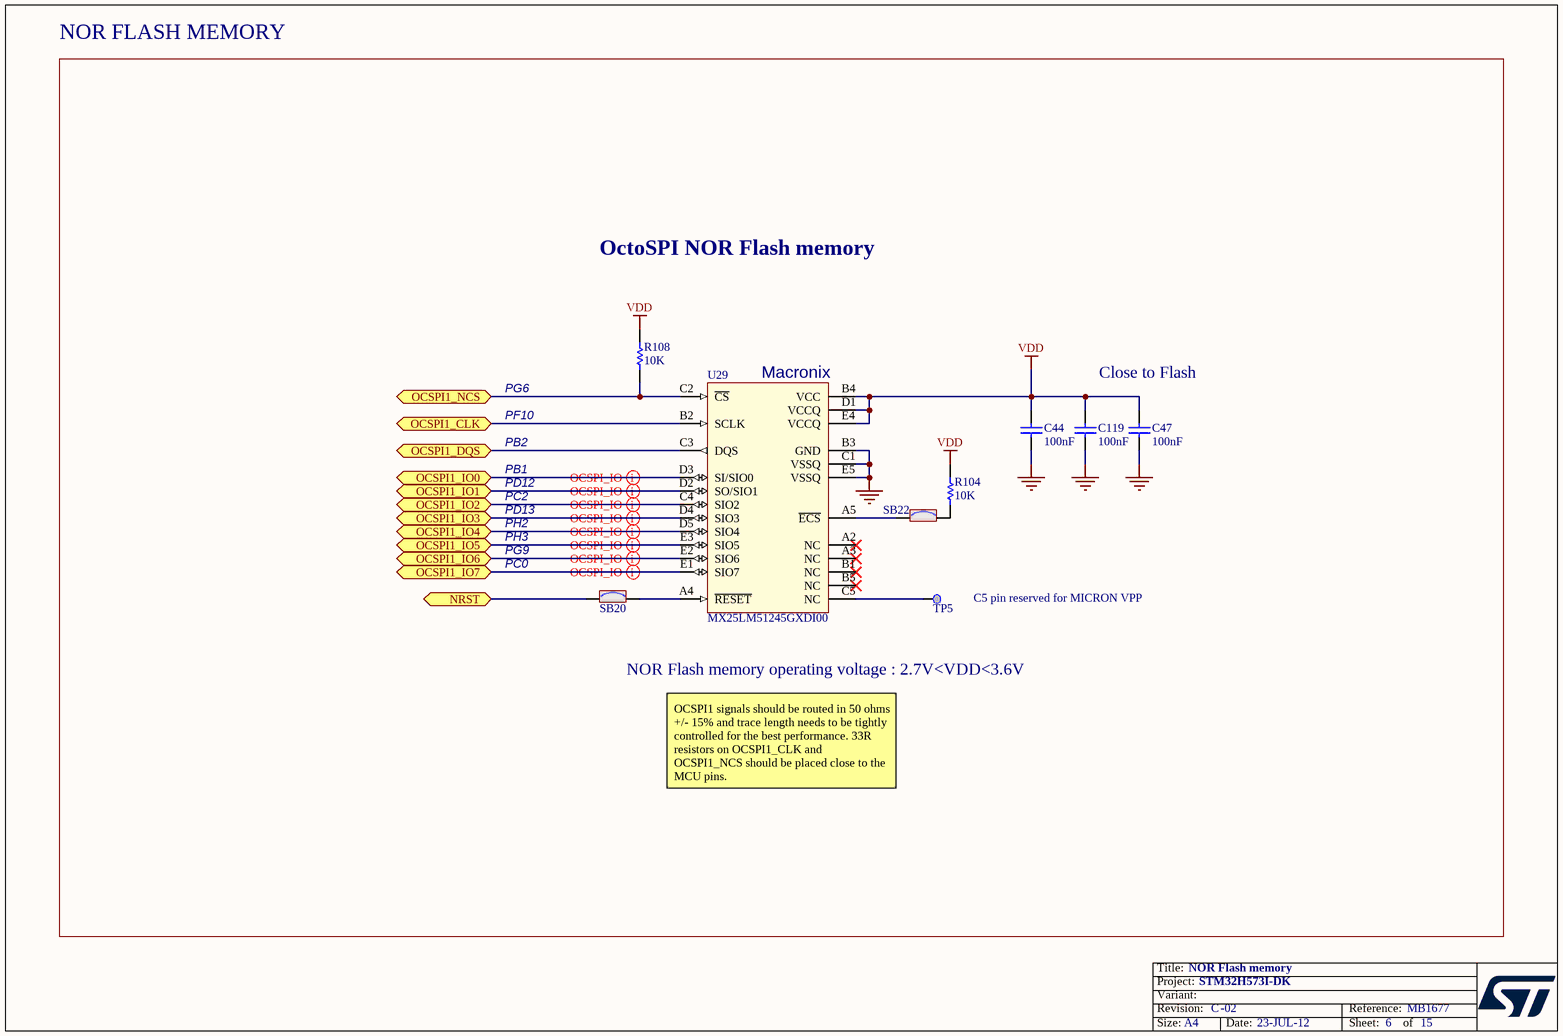
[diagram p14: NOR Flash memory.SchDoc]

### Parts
C44  value 100nF  [C0402]  (hidden comment: Capacitor)
C47  value 100nF  [C0402]  (hidden comment: Capacitor)
C119  value 100nF  [C0402]  (hidden comment: Capacitor)
R104  value 10K  [R0402]  (hidden comment: Resistor)
R108  value 10K  [R0402]  (hidden comment: Resistor)
SB20  SB_ON  [SOLDER-BRIDGE_R0603-0R]  (value not drawn)
SB22  SB_ON  [SOLDER-BRIDGE_R0603-0R]  (value not drawn)
TP5  Test Point  [TP_SMD_1MM]  (value not drawn)  (no BOM)
U29  MX25LM51245GXDI00  [ICC_BGA24_5X5-BALL-ARRAY_6X8_P1]

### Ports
NRST (bidir), OCSPI1_CLK (bidir), OCSPI1_DQS (bidir), OCSPI1_IO0 (bidir), OCSPI1_IO1 (bidir), OCSPI1_IO2 (bidir), OCSPI1_IO3 (bidir), OCSPI1_IO4 (bidir), OCSPI1_IO5 (bidir), OCSPI1_IO6 (bidir), OCSPI1_IO7 (bidir), OCSPI1_NCS (bidir)

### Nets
GND: C44.1 C47.1 C119.1 U29.B3(GND) U29.C1(VSSQ) U29.E5(VSSQ)
VDD: C44.2 C47.2 C119.2 R104.2 R108.1 U29.B4(VCC) U29.D1(VCCQ) U29.E4(VCCQ)
NRST: SB20.1 ; port NRST
OCSPI1_CLK: U29.B2(SCLK) ; port OCSPI1_CLK
OCSPI1_DQS: U29.C3(DQS) ; port OCSPI1_DQS
OCSPI1_IO0: U29.D3(SI/SIO0) ; port OCSPI1_IO0
OCSPI1_IO1: U29.D2(SO/SIO1) ; port OCSPI1_IO1
OCSPI1_IO2: U29.C4(SIO2) ; port OCSPI1_IO2
OCSPI1_IO3: U29.D4(SIO3) ; port OCSPI1_IO3
OCSPI1_IO4: U29.D5(SIO4) ; port OCSPI1_IO4
OCSPI1_IO5: U29.E3(SIO5) ; port OCSPI1_IO5
OCSPI1_IO6: U29.E2(SIO6) ; port OCSPI1_IO6
OCSPI1_IO7: U29.E1(SIO7) ; port OCSPI1_IO7
OCSPI1_NCS: R108.2 U29.C2(~{CS}) ; port OCSPI1_NCS
NetR104_1: R104.1 SB22.2
NetSB20_2: SB20.2 U29.A4(~{RESET})
NetSB22_1: SB22.1 U29.A5(~{ECS})
NetTP5_1: TP5.1 U29.C5(NC)

Not connected (* = marked no-connect by the designer): U29 A2(NC)* A3(NC)* B1(NC)* B5(NC)*

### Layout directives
rule Undefined; rule ? ; rule ? : OCSPI1_IO0, OCSPI1_IO1, OCSPI1_IO2, OCSPI1_IO3, OCSPI1_IO4, OCSPI1_IO5, OCSPI1_IO6, OCSPI1_IO7

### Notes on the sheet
- NOR FLASH MEMORY
- OctoSPI NOR Flash memory
- (near U29) Macronix
- Close to Flash
- PG6
- PF10
- PB2
- PB1
- PD13
- PC2
- PD12
- PH3
- PH2
- PG9
- PC0
- (near TP5) C5 pin reserved for MICRON VPP
- NOR Flash memory operating voltage : 2.7V<VDD<3.6V
- OCSPI1 signals should be routed in 50 ohms +/- 15% and trace length needs to be tightly controlled for the best performance. 33R resistors on OCSPI1_CLK and OCSPI1_NCS should be placed close to the MCU pins.

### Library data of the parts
C44 C47 C119 = MCD-00102: Capacitor, MLCC, 100nF, 16V, X7R, 10%, 0402, T=0,5mm; Manufacturer_Part_Number: CC0402KRX7R7BB104; Manufacturer: YAGEO; Alternate_Manufacturer_Part_Number: GCM155R71C104KA55D; Alternate_Manufacturer: MURATA; Provided_By: SUBCO
R104 R108 = MCD-00053: as R42 on sheet STM32_microcontroller_IOs
SB20 SB22 = MCD-00071: as SB28 on sheet USB-PD
TP5 = MCD-00074: Test Point 1mm; Part_Type: Misc; Part_Preference: Recommended
U29 = MCD-00246: Memory,Octo-SPI-NOR,512Mb,2048x16,133MHz,3V,DTR,BGA24, CMOS MXSMIO; Part_Type: IC; Manufacturer: MACRONIX; ECCN_US: 3A991.b.1.a; Provided_By: SUBCO

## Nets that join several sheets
1V8: Audio_Codec (8 pins), Board_power (JP2.3 SB10.2 TP2.1)
3V3: Audio_Codec (C67.2 CN2.2 CN2.19 U23.2), LCD (Q3.2 R99.1), Peripherals (6 pins), Arduino (CN14.5 R27.2), Ethernet (L1.2), Board_power (6 pins), STM32_microcontroller_power (SB14.1), STM32_microcontroller_IOs (C107.2 R93.1 X3.4), USB-PD (R56.2)
5V: LCD (R49.1 R103.1), Peripherals (CN3.6 CN3.15), Arduino (CN14.4), STLINK_V3EC (R64.2), Board_power (8 pins), USB-PD (SB28.1)
5V_STLK: STLINK_V3EC (6 pins), Board_power (JP4.1)
5V_UCPD: STLINK_V3EC (D4.1), Board_power (JP4.3), USB-PD (SB29.1)
5V_VIN: Arduino (R90.2), STLINK_V3EC (D3.1), Board_power (5 pins)
GND: Audio_Codec (34 pins), LCD (24 pins), Peripherals (7 pins), Arduino (6 pins), JTAG (13 pins), Ethernet (19 pins), STLINK_V3EC (121 pins), Board_power (15 pins), STM32_microcontroller_power (64 pins), STM32_microcontroller_IOs (9 pins), USB-PD (21 pins), microSDcard (10 pins), NOR Flash memory (6 pins)
VBUS_STLK: STLINK_V3EC (12 pins), Board_power (JP4.7)
VDD: Audio_Codec (7 pins), LCD (Q2.2 R100.1), Peripherals (B1.1 B1.2), Arduino (CN14.7), JTAG (CN1.1 CN18.1), Ethernet (7 pins), STLINK_V3EC (9 pins), Board_power (JP2.2), STM32_microcontroller_power (JP6.1), STM32_microcontroller_IOs (SW1.2), USB-PD (U30.2), microSDcard (8 pins), NOR Flash memory (8 pins)
VIN: Arduino (CN14.1), Board_power (C32.2 JP3.1 U8.3)
VREFP: Arduino (C110.1 R95.2), STM32_microcontroller_power (C35.2 C36.2 R21.2 U28.N1)
ARD_A0: Arduino (CN16.6), STM32_microcontroller_IOs (U28.R5)
ARD_A1: Arduino (CN16.5), STM32_microcontroller_IOs (U28.M5)
ARD_A2: Arduino (CN16.4), STM32_microcontroller_IOs (U28.P2)
ARD_A3: Arduino (CN16.3), STM32_microcontroller_IOs (U28.R3)
ARD_A4: Arduino (SB24.1), STM32_microcontroller_IOs (U28.P5)
ARD_A5: Arduino (SB23.1), STM32_microcontroller_IOs (U28.N7)
ARD_D0: Arduino (CN15.1), STM32_microcontroller_IOs (U28.N12)
ARD_D1: Arduino (CN15.2), STM32_microcontroller_IOs (U28.M10)
ARD_D2: Arduino (CN15.3), STM32_microcontroller_IOs (U28.A7)
ARD_D3: Arduino (CN15.4), STM32_microcontroller_IOs (U28.A6)
ARD_D4: Arduino (CN15.5), STM32_microcontroller_IOs (U28.J15)
ARD_D5: Arduino (CN15.6), STM32_microcontroller_IOs (U28.P15)
ARD_D6: Arduino (CN15.7), STM32_microcontroller_IOs (U28.N14)
ARD_D7: Arduino (CN15.8), STM32_microcontroller_IOs (U28.H15)
ARD_D8: Arduino (CN13.1), STM32_microcontroller_IOs (U28.G15)
ARD_D9: Arduino (CN13.2), STM32_microcontroller_IOs (U28.F15)
ARD_D10: Arduino (CN13.3), STM32_microcontroller_IOs (U28.N5)
ARD_D11: Arduino (CN13.4), STM32_microcontroller_IOs (U28.M14)
ARD_D12: Arduino (CN13.5), STM32_microcontroller_IOs (U28.B14)
ARD_D13: Arduino (CN13.6 SB15.1), STM32_microcontroller_IOs (U28.A15)
AUDIO_NRST: Audio_Codec (R73.1 U25.25), STM32_microcontroller_IOs (U28.F3)
DETECTn: Audio_Codec (CN2.10 R70.2 U23.3 U23.10), STM32_microcontroller_IOs (U28.C5)
I2C4_SCL: Audio_Codec (R80.1 U25.3), LCD (CN4.5), STM32_microcontroller_IOs (U28.B5), USB-PD (U30.18)
I2C4_SDA: Audio_Codec (R79.1 U25.2), LCD (CN4.4), STM32_microcontroller_IOs (U28.A4), USB-PD (U30.17)
IBUS_SENSE: STM32_microcontroller_IOs (U28.P7), USB-PD (U30.4)
JTCK: JTAG (R8.2), STLINK_V3EC (CN12.6 R69.2 U3.4 U27.11), STM32_microcontroller_IOs (U28.B13)
JTDI: JTAG (R7.2), STLINK_V3EC (CN12.10 R78.2 U3.1), STM32_microcontroller_IOs (U28.C13)
JTDO: JTAG (R9.2), STLINK_V3EC (CN12.8 R2.1 U3.3 U27.13), STM32_microcontroller_IOs (U28.B7)
JTMS: JTAG (R6.2), STLINK_V3EC (CN12.4 R72.2 U3.5), STM32_microcontroller_IOs (U28.E13)
LCD_A0_RS: LCD (CN7.21), STM32_microcontroller_IOs (U28.F2)
LCD_BL_CTRL: LCD (R55.2 U15.7), STM32_microcontroller_IOs (U28.A14)
LCD_CTP_INT: LCD (CN4.2), STM32_microcontroller_IOs (U28.H13)
LCD_CTP_RST: LCD (CN4.7), STM32_microcontroller_IOs (U28.H14)
LCD_D0: LCD (CN7.18), STM32_microcontroller_IOs (U28.K13)
LCD_D1: LCD (CN7.17), STM32_microcontroller_IOs (U28.J13)
LCD_D2: LCD (CN7.16), STM32_microcontroller_IOs (U28.B12)
LCD_D3: LCD (CN7.15), STM32_microcontroller_IOs (U28.A13)
LCD_D4: LCD (CN7.14), STM32_microcontroller_IOs (U28.R9)
LCD_D5: LCD (CN7.13), STM32_microcontroller_IOs (U28.P9)
LCD_D6: LCD (CN7.12), STM32_microcontroller_IOs (U28.N9)
LCD_D7: LCD (CN7.11), STM32_microcontroller_IOs (U28.R10)
LCD_D8: LCD (CN7.10), STM32_microcontroller_IOs (U28.P10)
LCD_D9: LCD (CN7.9), STM32_microcontroller_IOs (U28.R11)
LCD_D10: LCD (CN7.8), STM32_microcontroller_IOs (U28.P11)
LCD_D11: LCD (CN7.7), STM32_microcontroller_IOs (U28.N10)
LCD_D12: LCD (CN7.6), STM32_microcontroller_IOs (U28.N11)
LCD_D13: LCD (CN7.5), STM32_microcontroller_IOs (U28.M15)
LCD_D14: LCD (CN7.4), STM32_microcontroller_IOs (U28.L13)
LCD_D15: LCD (CN7.3), STM32_microcontroller_IOs (U28.K12)
LCD_NE1_CS: LCD (CN7.22 R44.1), STM32_microcontroller_IOs (U28.G13)
LCD_NOE: LCD (CN7.19), STM32_microcontroller_IOs (U28.B11)
LCD_NWE: LCD (CN7.20), STM32_microcontroller_IOs (U28.A11)
LCD_PWR_ON: LCD (R101.1 R102.1 R103.2), STM32_microcontroller_IOs (U28.G14)
LCD_RST: LCD (CN7.23 R41.2), STM32_microcontroller_IOs (U28.B15)
LCD_TE: LCD (CN7.2), STM32_microcontroller_IOs (U28.A12)
MEMS_LED: Audio_Codec (CN2.12), STM32_microcontroller_IOs (U28.B4)
NJTRST: JTAG (R5.2), STM32_microcontroller_IOs (U28.C7)
NRST: Arduino (CN14.6), JTAG (R4.2), Ethernet (U11.15), STLINK_V3EC (CN12.12 R68.2 U4.5), STM32_microcontroller_IOs (5 pins), NOR Flash memory (SB20.1)
OCS_25M: Ethernet (R38.2), STM32_microcontroller_IOs (R94.1)
OCSPI1_CLK: STM32_microcontroller_IOs (R105.1), NOR Flash memory (U29.B2)
OCSPI1_DQS: STM32_microcontroller_IOs (R107.1), NOR Flash memory (U29.C3)
OCSPI1_IO0: STM32_microcontroller_IOs (R118.1), NOR Flash memory (U29.D3)
OCSPI1_IO1: STM32_microcontroller_IOs (R119.2), NOR Flash memory (U29.D2)
OCSPI1_IO2: STM32_microcontroller_IOs (R109.2), NOR Flash memory (U29.C4)
OCSPI1_IO3: STM32_microcontroller_IOs (R115.2), NOR Flash memory (U29.D4)
OCSPI1_IO4: STM32_microcontroller_IOs (R114.2), NOR Flash memory (U29.D5)
OCSPI1_IO5: STM32_microcontroller_IOs (R120.2), NOR Flash memory (U29.E3)
OCSPI1_IO6: STM32_microcontroller_IOs (R117.2), NOR Flash memory (U29.E2)
OCSPI1_IO7: STM32_microcontroller_IOs (R116.2), NOR Flash memory (U29.E1)
OCSPI1_NCS: STM32_microcontroller_IOs (R106.2), NOR Flash memory (R108.2 U29.C2)
PDM_SAI1_CK1: Audio_Codec (U23.16), STM32_microcontroller_IOs (U28.L14)
PDM_SAI1_SD1: Audio_Codec (U23.5), STM32_microcontroller_IOs (U28.B10)
PDM_SAI1_SD2: Audio_Codec (CN2.5), STM32_microcontroller_IOs (U28.C3)
PDM_SAI1_SD3: Audio_Codec (CN2.7), STM32_microcontroller_IOs (U28.N3)
PMOD11: Peripherals (CN3.11 CN6.7), STM32_microcontroller_IOs (U28.M12)
PMOD12: Peripherals (CN3.12 CN6.8), STM32_microcontroller_IOs (U28.P13)
RMII_CRS_DV: Ethernet (R28.1), STM32_microcontroller_IOs (U28.R4)
RMII_MDC: Ethernet (U11.13), STM32_microcontroller_IOs (U28.L2)
RMII_MDIO: Ethernet (R34.1 U11.12), STM32_microcontroller_IOs (U28.M3)
RMII_REF_CLK: Ethernet (R37.1), STM32_microcontroller_IOs (U28.L3)
RMII_RX_ER: Ethernet (R29.1 U11.10), STM32_microcontroller_IOs (U28.F4)
RMII_RXD0: Ethernet (R31.1), STM32_microcontroller_IOs (U28.N4)
RMII_RXD1: Ethernet (R33.1), STM32_microcontroller_IOs (U28.P4)
RMII_TX_EN: Ethernet (U11.16), STM32_microcontroller_IOs (U28.C9)
RMII_TXD0: Ethernet (U11.17), STM32_microcontroller_IOs (U28.C8)
RMII_TXD1: Ethernet (U11.18), STM32_microcontroller_IOs (U28.B8)
SAI2_FS_A: Audio_Codec (U25.1), STM32_microcontroller_IOs (U28.A1)
SAI2_MCLK_A: Audio_Codec (U25.30), STM32_microcontroller_IOs (U28.B3)
SAI2_SCK_A: Audio_Codec (U25.31), STM32_microcontroller_IOs (U28.A2)
SAI2_SD_A: Audio_Codec (U25.32), STM32_microcontroller_IOs (U28.C4)
SAI2_SD_B: Audio_Codec (U25.29), STM32_microcontroller_IOs (U28.A9)
SDIO1_CK: STM32_microcontroller_IOs (U28.C11), microSDcard (CN5.5 U5.2 U5.9)
SDIO1_CMD: STM32_microcontroller_IOs (U28.C10), microSDcard (CN5.3 R13.1 U5.1 U5.10)
SDIO1_D0: STM32_microcontroller_IOs (U28.F14), microSDcard (CN5.7 R12.1 U5.4 U5.7)
SDIO1_D1: STM32_microcontroller_IOs (U28.F13), microSDcard (CN5.8 R11.1 U5.5 U5.6)
SDIO1_D2: STM32_microcontroller_IOs (U28.D12), microSDcard (CN5.1 R18.1 U7.1 U7.10)
SDIO1_D3: STM32_microcontroller_IOs (U28.C12), microSDcard (CN5.2 R16.1 U7.2 U7.9)
STMOD#1: Peripherals (SB5.1 SB9.1), STM32_microcontroller_IOs (U28.H1)
STMOD#2: Peripherals (SB7.1 SB8.1), STM32_microcontroller_IOs (U28.J3)
STMOD#3: Peripherals (SB3.1 SB6.1), STM32_microcontroller_IOs (U28.K2)
STMOD#4: Peripherals (SB2.1 SB4.1), STM32_microcontroller_IOs (U28.H2)
STMOD#8-MOSIs: Peripherals (CN3.8), STM32_microcontroller_IOs (U28.N13)
STMOD#9-MISOs: Peripherals (CN3.9), STM32_microcontroller_IOs (U28.P14)
STMOD#13-ADC: Peripherals (CN3.13), STM32_microcontroller_IOs (U28.R6)
STMOD#14-PWM: Peripherals (CN3.14), STM32_microcontroller_IOs (U28.M13)
STMOD#17: Peripherals (CN3.17), STM32_microcontroller_IOs (U28.G2)
STMOD#18: Peripherals (CN3.18), STM32_microcontroller_IOs (U28.L12)
STMOD#19: Peripherals (CN3.19), STM32_microcontroller_IOs (U28.R1)
STMOD#20: Peripherals (CN3.20), STM32_microcontroller_IOs (U28.P1)
TRACECLK: JTAG (CN18.12 U17.1), STM32_microcontroller_IOs (U28.D4)
TRACED0: JTAG (CN18.14 R97.1 U16.4), STM32_microcontroller_IOs (U28.B2)
TRACED1: JTAG (CN18.16 R98.1 U16.3), STM32_microcontroller_IOs (U28.A8)
TRACED2: JTAG (CN18.18 U16.1), STM32_microcontroller_IOs (U28.D3)
TRACED3: JTAG (CN18.20 U16.5), STM32_microcontroller_IOs (U28.C2)
UCPD_CC1: STM32_microcontroller_IOs (U28.R15), USB-PD (U30.1)
UCPD_CC2: STM32_microcontroller_IOs (U28.N15), USB-PD (U30.3)
UCPD_FLT: STM32_microcontroller_IOs (U28.P8), USB-PD (U30.19)
UCPD_PWR: STM32_microcontroller_IOs (U28.R8), USB-PD (U30.20)
USB_FS_N: STM32_microcontroller_IOs (U28.D15), USB-PD (CN17.A7 CN17.B7 U31.1 U31.6)
USB_FS_P: STM32_microcontroller_IOs (U28.C15), USB-PD (CN17.A6 CN17.B6 U31.3 U31.4)
uSD_Detect: STM32_microcontroller_IOs (U28.D13), microSDcard (CN5.9 R10.1)
USER_LED1: Peripherals (R26.1), STM32_microcontroller_IOs (U28.E1)
USER_LED2: Peripherals (R25.1), STM32_microcontroller_IOs (U28.E2)
USER_LED3: Peripherals (R24.1), STM32_microcontroller_IOs (U28.F1)
USER_LED4: Peripherals (R22.1), STM32_microcontroller_IOs (U28.G1)
VBUS_SENSE: STM32_microcontroller_IOs (U28.R7), USB-PD (C122.2 R124.2 R125.1)
WAKEUP: Peripherals (5 pins), STM32_microcontroller_IOs (U28.E3)

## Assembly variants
H573I: not fitted C26 C34 C60 C61 C96 C115 C125 CN1 CN11 D3 D4 R10 R44 R95 R99 R100 R138 R139 SB2 SB5 SB6 SB8 SB18 SB21 SB22 SB25 U21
